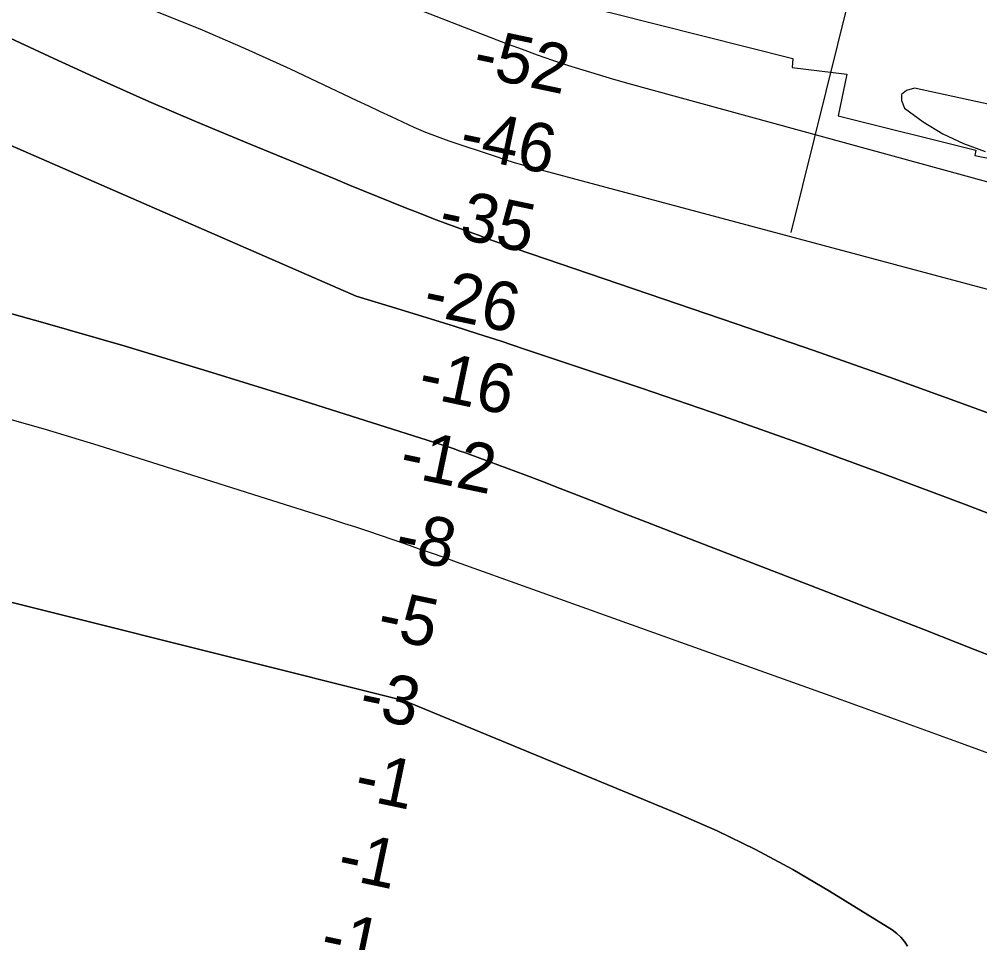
# Model space of a CAD drawing. Extents: x 3219052 to 3256913, y 800770 to 826146.
# Drawn here: x 3234706 to 3235887, y 815700 to 816836 of the extents above; entities that cross this region are included whole.
import ezdxf

# ---------------------------------------------------------------- set-up
doc = ezdxf.new("R2010")
doc.units = 0
for name, color, linetype in [('V-RIVR-RANG', 7, 'Continuous'), ('V-RRAP-RVMT', 7, 'Continuous'), ('V-TOPO-DPTH', 7, 'Continuous'), ('V-TOPO-MAJR', 7, 'Continuous'), ('V-TOPO-MINR', 7, 'Continuous')]:
    doc.layers.add(name, color=color, linetype=linetype)

msp = doc.modelspace()

# ---------------------------------------------------------------- linework, layer by layer
at = {"layer": 'V-RIVR-RANG'}
msp.add_line((3235818, 817233.9), (3235654.8, 816573.8), dxfattribs=at)
at = {"layer": 'V-RRAP-RVMT'}
msp.add_lwpolyline([(3234922.9, 816973.5), (3234916.5, 816943.3), (3235223.7, 816896.2), (3235223.2, 816892.8), (3235434.1, 816844.2), (3235657.1, 816787.8), (3235656.2, 816776.9), (3235723.5, 816768.8), (3235712.9, 816717.3), (3235882.4, 816675.1), (3235881.2, 816668.8), (3235908.1, 816663.3), (3235902.3, 816638.7), (3235980.3, 816621.1)], dxfattribs=at)
at = {"layer": 'V-TOPO-DPTH'}
for points in [[(3234659.1, 816829.2), (3234748.5, 816787.8), (3234806.7, 816761.2), (3234865.1, 816735.2), (3234923.9, 816710), (3234982.8, 816685.3), (3235094.6, 816639.3), (3235111.8, 816632.2), (3235129, 816625.2), (3235146.2, 816618.2), (3235163.4, 816611.2), (3235180.7, 816604.2), (3235198, 816597.5), (3235215.4, 816590.8), (3235232.8, 816584.3), (3235270.4, 816570.5), (3235282, 816566.3), (3235293.7, 816562.1), (3235305.3, 816558), (3235317, 816554), (3235587.4, 816461.8), (3235681.8, 816429.2), (3235776.1, 816396), (3235870, 816362.1), (3235963.8, 816327.7)], [(3235963.8, 816327.7), (3235870, 816362.1), (3235776.1, 816396), (3235681.8, 816429.2), (3235587.4, 816461.8), (3235317, 816554), (3235305.3, 816558), (3235293.7, 816562.1), (3235282, 816566.3), (3235270.4, 816570.5), (3235232.8, 816584.3), (3235215.4, 816590.8), (3235198, 816597.5), (3235180.7, 816604.2), (3235163.4, 816611.2), (3235146.2, 816618.2), (3235129, 816625.2), (3235111.8, 816632.2), (3235094.6, 816639.3), (3234982.8, 816685.3), (3234923.9, 816710), (3234865.1, 816735.2), (3234806.7, 816761.2), (3234748.5, 816787.8), (3234659.1, 816829.2)], [(3234478.2, 816775.4), (3235120.2, 816495.7), (3235170, 816480.4), (3235211.7, 816467.6), (3235240.7, 816458.6), (3235269.6, 816449.5), (3235298.4, 816440.1), (3235327.2, 816430.6), (3235470.9, 816382.4), (3235571.3, 816348.1), (3235671.3, 816312.9), (3235770.9, 816276.4), (3235870.2, 816239), (3236107.4, 816148)], [(3236107.4, 816148), (3235870.2, 816239), (3235770.9, 816276.4), (3235671.3, 816312.9), (3235571.3, 816348.1), (3235470.9, 816382.4), (3235327.2, 816430.6), (3235298.4, 816440.1), (3235269.6, 816449.5), (3235240.7, 816458.6), (3235211.7, 816467.6), (3235170, 816480.4), (3235120.2, 816495.7), (3234478.2, 816775.4)], [(3234633, 816491.7), (3234734.8, 816463.3), (3234836.2, 816434), (3234937.3, 816403.5), (3235038.2, 816372.2), (3235224.4, 816313.1), (3235231.9, 816310.6), (3235239.5, 816308.1), (3235246.9, 816305.5), (3235254.4, 816302.8), (3235283.5, 816292.2), (3235305.4, 816284.1), (3235327.4, 816275.9), (3235349.2, 816267.6), (3235371.1, 816259.1), (3235387, 816252.9), (3235416.7, 816241.3), (3235446.5, 816229.7), (3235476.3, 816218.1), (3235506, 816206.6), (3235691.5, 816134.9), (3235754.9, 816110.4), (3235818.3, 816085.7), (3235881.6, 816060.9), (3235944.9, 816036)], [(3235944.9, 816036), (3235881.6, 816060.9), (3235818.3, 816085.7), (3235754.9, 816110.4), (3235691.5, 816134.9), (3235506, 816206.6), (3235476.3, 816218.1), (3235446.5, 816229.7), (3235416.7, 816241.3), (3235387, 816252.9), (3235371.1, 816259.1), (3235349.2, 816267.6), (3235327.4, 816275.9), (3235305.4, 816284.1), (3235283.5, 816292.2), (3235254.4, 816302.8), (3235246.9, 816305.5), (3235239.5, 816308.1), (3235231.9, 816310.6), (3235224.4, 816313.1), (3235038.2, 816372.2), (3234937.3, 816403.5), (3234836.2, 816434), (3234734.8, 816463.3), (3234633, 816491.7)], [(3235798.1, 815696.2), (3235794.4, 815702.1), (3235790.1, 815707.4), (3235785, 815712), (3235779.4, 815716.2), (3235702.3, 815763.9), (3235657.1, 815790.4), (3235611.2, 815815.3), (3235564.1, 815838), (3235516.2, 815859.1), (3235185.7, 815995.4), (3235184.2, 815996), (3235182.7, 815996.6), (3235178, 815998.3), (3235173.7, 815999.7), (3235173.4, 815999.7), (3234531.6, 816160.4)], [(3234531.6, 816160.4), (3235173.4, 815999.7), (3235173.7, 815999.7), (3235178, 815998.3), (3235182.7, 815996.6), (3235184.2, 815996), (3235185.7, 815995.4), (3235516.2, 815859.1), (3235564.1, 815838), (3235611.2, 815815.3), (3235657.1, 815790.4), (3235702.3, 815763.9), (3235779.4, 815716.2), (3235785, 815712), (3235790.1, 815707.4), (3235794.4, 815702.1), (3235798.1, 815696.2)]]:
    msp.add_lwpolyline(points, dxfattribs=at)
at = {"layer": 'V-TOPO-MAJR'}
msp.add_lwpolyline([(3234573.2, 816955.4), (3234814.5, 816868.4), (3234871.4, 816847), (3234927.9, 816824.4), (3234983.7, 816800.3), (3235039, 816775.1), (3235121.1, 816736.3), (3235135.1, 816729.7), (3235149, 816723.1), (3235163, 816716.4), (3235177, 816709.8), (3235191, 816703.4), (3235205.2, 816697.4), (3235219.7, 816691.9), (3235234.2, 816686.7), (3235291, 816667.6), (3235302.8, 816663.8), (3235314.6, 816660.1), (3235326.5, 816656.6), (3235338.4, 816653.3), (3236097.4, 816450.6)], dxfattribs=at)
at = {"layer": 'V-TOPO-MINR'}
for points in [[(3234689.2, 817033.2), (3234712.4, 817025.1), (3234735.6, 817017), (3234852.7, 816975.6), (3235015.8, 816916.6), (3235097, 816886.3), (3235178, 816855.4), (3235306, 816806.1), (3235324.4, 816799.2), (3235342.9, 816792.4), (3235361.4, 816786), (3235380.1, 816779.7), (3235398.9, 816773.8), (3235417.7, 816768), (3235436.5, 816762.5), (3235455.5, 816757.2), (3236164.9, 816562.8), (3236200, 816553.7), (3236235.3, 816545.4), (3236270.7, 816538.2), (3236306.4, 816531.6), (3236627.4, 816477.7), (3236636.5, 816480.6), (3236642.1, 816485.2)], [(3234659.1, 816829.2), (3234748.5, 816787.8), (3234806.7, 816761.2), (3234865.1, 816735.2), (3234923.9, 816710), (3234982.8, 816685.3), (3235094.6, 816639.3), (3235111.8, 816632.2), (3235129, 816625.2), (3235146.2, 816618.2), (3235163.4, 816611.2), (3235180.7, 816604.2), (3235198, 816597.5), (3235215.4, 816590.8), (3235232.8, 816584.3), (3235270.4, 816570.5), (3235282, 816566.3), (3235293.7, 816562.1), (3235305.3, 816558), (3235317, 816554), (3235587.4, 816461.8), (3235681.8, 816429.2), (3235776.1, 816396), (3235870, 816362.1), (3235963.8, 816327.7)], [(3234478.2, 816775.4), (3235120.2, 816495.7), (3235170, 816480.4), (3235211.7, 816467.6), (3235240.7, 816458.6), (3235269.6, 816449.5), (3235298.4, 816440.1), (3235327.2, 816430.6), (3235470.9, 816382.4), (3235571.3, 816348.1), (3235671.3, 816312.9), (3235770.9, 816276.4), (3235870.2, 816239), (3236107.4, 816148)], [(3236227.4, 816660.1), (3235806.7, 816751.4), (3235796.9, 816748.6), (3235791, 816743.8), (3235790.9, 816736.2), (3235794.7, 816726.8), (3235817.6, 816709.9), (3235841.6, 816695.1), (3235867.2, 816683.4), (3235893.9, 816673.7)], [(3234633, 816491.7), (3234734.8, 816463.3), (3234836.2, 816434), (3234937.3, 816403.5), (3235038.2, 816372.2), (3235224.4, 816313.1), (3235231.9, 816310.6), (3235239.5, 816308.1), (3235246.9, 816305.5), (3235254.4, 816302.8), (3235283.5, 816292.2), (3235305.4, 816284.1), (3235327.4, 816275.9), (3235349.2, 816267.6), (3235371.1, 816259.1), (3235387, 816252.9), (3235416.7, 816241.3), (3235446.5, 816229.7), (3235476.3, 816218.1), (3235506, 816206.6), (3235691.5, 816134.9), (3235754.9, 816110.4), (3235818.3, 816085.7), (3235881.6, 816060.9), (3235944.9, 816036)], [(3234672.2, 816350.6), (3234737.5, 816332.1), (3234802.5, 816312.5), (3235017.4, 816244.4), (3235039.4, 816237.4), (3235061.5, 816230.4), (3235083.6, 816223.3), (3235105.6, 816216.2), (3235118.2, 816212.2), (3235133.9, 816207), (3235149.6, 816201.8), (3235165.3, 816196.5), (3235180.9, 816191), (3235196.5, 816185.5), (3235212.2, 816180), (3235227.8, 816174.5), (3235243.3, 816168.9), (3235524.8, 816068.2), (3235610.9, 816037.3), (3235696.9, 816006.4), (3235782.9, 815975.3), (3235868.9, 815944.1), (3236005.5, 815894.4)], [(3234531.6, 816160.4), (3235173.4, 815999.7), (3235173.7, 815999.7), (3235178, 815998.3), (3235182.7, 815996.6), (3235184.2, 815996), (3235185.7, 815995.4), (3235516.2, 815859.1), (3235564.1, 815838), (3235611.2, 815815.3), (3235657.1, 815790.4), (3235702.3, 815763.9), (3235779.4, 815716.2), (3235785, 815712), (3235790.1, 815707.4), (3235794.4, 815702.1), (3235798.1, 815696.2)]]:
    msp.add_lwpolyline(points, dxfattribs=at)

# ---------------------------------------------------------------- texts
at = {"layer": 'V-RIVR-RANG'}
for s, p in [('-52', (3235261.5, 816767.7)), ('-46', (3235244.8, 816669.1)), ('-35', (3235219.3, 816572.2)), ('-26', (3235200.3, 816474)), ('-16', (3235194.2, 816373.1)), ('-12', (3235171.1, 816275.8)), ('-8', (3235165.5, 816174.8)), ('-5', (3235143.7, 816077.2)), ('-3', (3235121.4, 815979.7)), ('-1', (3235115.6, 815878.7)), ('-1', (3235094.7, 815780.9)), ('-1', (3235073.9, 815683.1))]:
    msp.add_text(s, height=60, rotation=348.0996, dxfattribs=at).set_placement(p)

doc.saveas('drawing.dxf')
